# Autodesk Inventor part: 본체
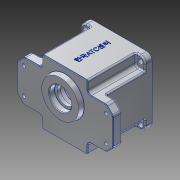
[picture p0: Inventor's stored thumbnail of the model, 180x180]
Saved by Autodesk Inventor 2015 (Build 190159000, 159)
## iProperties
Created: 2016-02
Part Number: 본체
Material: Aluminum 6061
Document SubType Name: Modeling
Designer: Administrator
Density: 2.7 g/cm^3
Appearance: Aluminum - Flat
Mass: 874.124 g
Surface Area: 762.764 cm^2
Volume: 323.75 cm^3
Author: Administrator
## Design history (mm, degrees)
sketch "Sketch1"
  geometry: L1 (-47, -47)-(47, -47); L2 (47, -47)-(47, 47); L3 (47, 47)-(-47, 47); L4 (-47, 47)-(-47, -47); L5 (-47, -47)-(47, 47); L6 (47, -47)-(-47, 47); 1 further point
  constraints: 12 end point, 2 midpoint, 2 parallel, 1 horizontal, 1 perpendicular
  dimensions: "d0" = 94 distance of L3.end L2.end; "d1" = 94 distance of L2.end L1.end
extrude "Extrusion1" new body sketch "Sketch1" distance "d2" = 80; taper "d3" = 0 deg
sketch "Sketch2"
  geometry: L1 (33, -47)-(-33, -47); L2 (-33, -47)-(-33, 47); L3 (-33, 47)-(33, 47); L4 (33, 47)-(33, -47); L5 (33, -47)-(-33, 47); L6 (-33, -47)-(33, 47); L7 (-47, 47)-(47, 47) reference; L8 (47, -30)-(-47, -30); L9 (-47, -30)-(-47, 30); L10 (-47, 30)-(47, 30); L11 (47, 30)-(47, -30); L12 (47, -30)-(-47, 30); L13 (-47, -30)-(47, 30); L14 (47, 47)-(47, -47) reference; L15 (47, -47)-(-47, -47) reference; L16 (-47, -47)-(-47, 47) reference; L17 (-47, 47)-(47, 47) reference; L18 (47, 47)-(47, -47) reference; 1 further point
  constraints: 24 end point, 4 midpoint, 4 parallel, 2 collinear, 2 horizontal, 2 perpendicular
  dimensions: "d4" = 66 distance of L2.end L3.end; "d5" = 60 distance of L8.end L9.end
extrude "Extrusion2" cut sketch "Sketch2" distance "d6" = 70; taper "d7" = 0 deg
sketch "Sketch3"
  geometry: L1 (70, -30)-(-70, -30); L2 (-70, -30)-(-70, 30); L3 (-70, 30)-(70, 30); L4 (70, 30)-(70, -30); L5 (70, -30)-(-70, 30); L6 (-70, -30)-(70, 30); 1 further point
  constraints: 12 end point, 2 midpoint, 2 parallel, 1 horizontal, 1 perpendicular
  dimensions: "d8" = 140 distance of L2.end L3.end; "d9" = 60 distance of L1.end L2.end
extrude "Extrusion3" join sketch "Sketch3" distance "d10" = 13; taper "d11" = 0 deg
fillet "Fillet1" dims "d12" = 8
chamfer "Chamfer1" distance "d13" = 10; stored, may be unused: second distance "d14" = 2, angle "d15" = 45 deg
sketch "Sketch4"
  geometry: C1 r 28 at (0, 11); 1 further point
  constraints: 1 centre point, 1 vertical alignment
  dimensions: "d16" = 56 diameter of C1; "d17" = 11 distance of C1.centre point (0, 0)
extrude "Extrusion4" join sketch "Sketch4" distance "d18" = 7; taper "d19" = -10 deg
sketch "Sketch5"
  geometry: C1 r 43 at (0, 0); 1 further point
  constraints: 1 centre point, 1 coincident
  dimensions: "d20" = 86 diameter of C1
extrude "Extrusion5" cut sketch "Sketch5" distance "d21" = 9; taper "d22" = 0 deg
sketch "Sketch6"
  geometry: C1 r 40 at (0, 0); 1 further point
  constraints: 1 centre point, 1 coincident
  dimensions: "d23" = 80 diameter of C1
extrude "Extrusion6" cut sketch "Sketch6" distance "d24" = 62; taper "d25" = 0 deg
sketch "Sketch7"
  geometry: C1 r 21 at (0, -11); C2 r 15 at (0, 20); 1 further point
  constraints: 2 centre point, 2 vertical alignment
  dimensions: "d26" = 21 radius of C1; "d27" = 15 radius of C2; "d28" = 11 distance of point (0, 0) C1.centre; "d29" = 20 distance of C2.centre point (0, 0)
extrude "Extrusion7" join sketch "Sketch7" distance "d30" = 7; taper "d31" = 0 deg
hole "Hole1" diameter "d34" = 19; stored, may be unused: countersink angle "d38" = 90 deg, drill point angle "d40" = 0 deg; dims "d32" = 10, "d33" = 10, "d35" = 6, "d36" = 22, "d37" = 7, "d39" = 8
sketch "Sketch8"
  geometry: C1 r 17.5 at (0, -11); A1 r 21 centre (0, -11) between (-8.978, 7.984) and (8.978, 7.984) reference; 1 further point
  constraints: 1 centre point, 1 coincident
  dimensions: "d41" = 35 diameter of C1
extrude "Extrusion8" cut sketch "Sketch8" distance "d42" = 10; taper "d43" = 0 deg
hole "Hole2" diameter "d46" = 25; stored, may be unused: countersink angle "d50" = 90 deg, drill point angle "d52" = 0 deg; dims "d44" = 10, "d45" = 10, "d47" = 6, "d48" = 32, "d49" = 8, "d51" = 13
fillet "Fillet2" dims "d53" = 3
sketch "Sketch9"
  geometry: L1 (-35.777, -4)-(-39.799, -4); L2 (-35.777, 4)-(-39.799, 4); L3 (39.799, -4)-(35.777, -4); L4 (39.799, 4)-(35.777, 4); A1 r 36 centre (0, 0) between (36, 0) and (-36, 0); A2 r 40 centre (0, 0) between (-39.799, -4) and (-39.799, 4) reference; A3 r 4 centre (36, 0) between (36, 4) and (36, -4); A4 r 4 centre (-36, 0) between (-36, -4) and (-36, 4); A5 r 40 centre (0, 0) between (39.799, -4) and (39.799, 4); A6 r 40 centre (0, 0) between (-39.799, 4) and (-39.799, -4); 1 further point
  constraints: 18 point on circle, 8 end point, 5 centre point, 4 horizontal, 4 point on line, 4 tangent, 3 coincident, 2 horizontal alignment
  dimensions: "d54" = 36 radius of A1; "d55" = 4 radius of A3; "d56" = 4 radius of A4
extrude "Extrusion9" join sketch "Sketch9" stored distance "d57" = 10; taper "d58" = 0 deg
fillet "Fillet3" dims "d59" = 3.5
sketch "Sketch10"
  geometry: A1 r 4 centre (36, 0) between (35.852, 3.997) and (35.852, -3.997) reference; A2 r 4 centre (-36, 0) between (-35.852, -3.997) and (-35.852, 3.997) reference; 3 further points
  constraints: 2 coincident
hole "Hole3" sketch "Sketch10" at (36, 0), (-36, 0) diameter "d60" = 3.242; stored, may be unused: countersink angle "d64" = 90 deg, drill point angle "d66" = 118 deg; dims "d61" = 7, "d62" = 32, "d63" = 8, "d65" = 9
sketch "Sketch12"
  geometry: 5 further points
  constraints: 2 horizontal alignment, 2 vertical alignment
  dimensions: "d70" = 120 distance of point (60, -19) point (-60, -19); "d71" = 60 horizontal distance of point (0, 0) point (-60, -19); "d72" = 38 distance of point (-60, 19) point (-60, -19); "d73" = 19 vertical distance of point (0, 0) point (-60, -19)
hole "Hole4" sketch "Sketch12" at (60, -19), (60, 19), (-60, -19), (-60, 19) diameter "d74" = 5; stored, may be unused: countersink angle "d78" = 90 deg, drill point angle "d80" = 0 deg; dims "d75" = 6, "d76" = 9, "d77" = 4, "d79" = 13
sketch "Sketch13" dims "d0" = 94, "d1" = 94
  geometry: L1 (0, 0)-(78, 0) reference; 2 further points
  constraints: 1 vertical alignment, 1 other
  dimensions: "d82" = 40 distance from line of L1 point (39, -40)
emboss "Emboss1" sketch "Sketch13" dims "d0" = 94, "d1" = 94, "d83" = 0.5, "d84" = 0
fillet "Fillet4" dims "d85" = 0.3
chamfer "Chamfer2" distance "d86" = 1; stored, may be unused: second distance "d87" = 2, angle "d88" = 45 deg
fillet "Fillet5" dims "d89" = 5
sketch "Sketch14"
  geometry: L1 (-47, -39)-(-47, 39) reference; L2 (-39, 47)-(39, 47) reference; L3 (47, 39)-(47, -39) reference; L4 (39, -47)-(-39, -47) reference; C1 r 3.5 at (-40, 40); C2 r 3.5 at (40, 40); C3 r 3.5 at (40, -40); C4 r 3.5 at (-40, -40); A1 r 8 centre (-39, 39) between (-39, 47) and (-47, 39) reference; A2 r 8 centre (39, 39) between (47, 39) and (39, 47) reference; A3 r 8 centre (39, -39) between (39, -47) and (47, -39) reference; A4 r 8 centre (-39, -39) between (-47, -39) and (-39, -47) reference; A5 r 8 centre (-39, 39) between (-39, 47) and (-47, 39) reference; A6 r 8 centre (39, 39) between (47, 39) and (39, 47) reference; A7 r 8 centre (39, -39) between (39, -47) and (47, -39) reference; 1 further point
  constraints: 4 centre point, 2 horizontal alignment, 2 vertical alignment
  dimensions: "d100" = 7 diameter of C1; "d101" = 7 diameter of C2; "d102" = 7 diameter of C3; "d103" = 7 diameter of C4; "d104" = 80 distance of C2.centre C1.centre; "d105" = 40 horizontal distance of point (0, 0) C2.centre; "d106" = 80 distance of C1.centre C4.centre; "d107" = 40 horizontal distance of point (0, 0) C4.centre
  node "Projected Loop3"
fillet "Fillet6" dims "d96" = 2
sketch "Sketch15"
  geometry: L1 (31, -47)-(-31, -47) reference; L2 (33, -45)-(33, -35) reference; L3 (38, -30)-(57.929, -30) reference; L4 (68.536, -21.464)-(61.464, -28.536) reference; L5 (70, 17.929)-(70, -17.929) reference; L6 (61.464, 28.536)-(68.536, 21.464) reference; L7 (57.929, 30)-(38, 30) reference; L8 (33, 35)-(33, 45) reference; L9 (-31, 47)-(31, 47) reference; L10 (-33, 45)-(-33, 35) reference; L11 (-38, 30)-(-57.929, 30) reference; L12 (-68.536, 21.464)-(-61.464, 28.536) reference; L13 (-70, -17.929)-(-70, 17.929) reference; L14 (-61.464, -28.536)-(-68.536, -21.464) reference; L15 (-57.929, -30)-(-38, -30) reference; L16 (-33, -35)-(-33, -45) reference; L17 (32, 45)-(32, 35); L18 (38, 29)-(57.929, 29); L19 (60.757, 27.828)-(67.828, 20.757); L20 (69, 17.929)-(69, -17.929); L21 (67.828, -20.757)-(60.757, -27.828); L22 (57.929, -29)-(38, -29); L23 (32, -35)-(32, -45); L24 (31, -46)-(-31, -46); L25 (-32, -45)-(-32, -35); L26 (-38, -29)-(-57.929, -29); L27 (-60.757, -27.828)-(-67.828, -20.757); L28 (-69, -17.929)-(-69, 17.929); L29 (-67.828, 20.757)-(-60.757, 27.828); L30 (-57.929, 29)-(-38, 29); L31 (-32, 35)-(-32, 45); L32 (-31, 46)-(31, 46); C1 r 28.252 at (0, 11) reference; C2 r 2.5 at (-60, 19) reference; C3 r 2.5 at (60, 19) reference; C4 r 2.5 at (60, -19) reference; C5 r 2.5 at (-60, -19) reference; A1 r 2 centre (-31, -45) between (-33, -45) and (-31, -47) reference; A2 r 2 centre (31, -45) between (31, -47) and (33, -45) reference; A3 r 5 centre (38, -35) between (38, -30) and (33, -35) reference; A4 r 5 centre (57.929, -25) between (57.929, -30) and (61.464, -28.536) reference; A5 r 5 centre (65, -17.929) between (68.536, -21.464) and (70, -17.929) reference; A6 r 5 centre (65, 17.929) between (70, 17.929) and (68.536, 21.464) reference; A7 r 5 centre (57.929, 25) between (61.464, 28.536) and (57.929, 30) reference; A8 r 5 centre (38, 35) between (33, 35) and (38, 30) reference; A9 r 2 centre (31, 45) between (33, 45) and (31, 47) reference; A10 r 2 centre (-31, 45) between (-31, 47) and (-33, 45) reference; A11 r 5 centre (-38, 35) between (-38, 30) and (-33, 35) reference; A12 r 5 centre (-57.929, 25) between (-57.929, 30) and (-61.464, 28.536) reference; A13 r 5 centre (-65, 17.929) between (-68.536, 21.464) and (-70, 17.929) reference; A14 r 5 centre (-65, -17.929) between (-70, -17.929) and (-68.536, -21.464) reference; A15 r 5 centre (-57.929, -25) between (-61.464, -28.536) and (-57.929, -30) reference; A16 r 5 centre (-38, -35) between (-33, -35) and (-38, -30) reference; A17 r 1 centre (31, 45) between (32, 45) and (31, 46); A18 r 6 centre (38, 35) between (32, 35) and (38, 29); A19 r 4 centre (57.929, 25) between (60.757, 27.828) and (57.929, 29); A20 r 4 centre (65, 17.929) between (69, 17.929) and (67.828, 20.757); A21 r 4 centre (65, -17.929) between (67.828, -20.757) and (69, -17.929); A22 r 4 centre (57.929, -25) between (57.929, -29) and (60.757, -27.828); A23 r 6 centre (38, -35) between (38, -29) and (32, -35); A24 r 1 centre (31, -45) between (31, -46) and (32, -45); A25 r 1 centre (-31, -45) between (-32, -45) and (-31, -46); A26 r 6 centre (-38, -35) between (-32, -35) and (-38, -29); A27 r 4 centre (-57.929, -25) between (-60.757, -27.828) and (-57.929, -29); A28 r 4 centre (-65, -17.929) between (-69, -17.929) and (-67.828, -20.757); A29 r 4 centre (-65, 17.929) between (-67.828, 20.757) and (-69, 17.929); A30 r 4 centre (-57.929, 25) between (-57.929, 29) and (-60.757, 27.828); A31 r 6 centre (-38, 35) between (-38, 29) and (-32, 35); A32 r 1 centre (-31, 45) between (-31, 46) and (-32, 45); 1 further point
  constraints: 32 end point, 32 point on circle, 16 centre point, 31 other
  dimensions: "d97" = 1 distance between parallel lines of L9 L32
extrude "Extrusion12" cut sketch "Sketch15" distance "d98" = 1; taper "d99" = 0 deg
extrude "Extrusion13" cut sketch "Sketch14" stored distance "d108" = 1; taper "d109" = 0 deg
body "Solid1"
node "Projected Loop1"
node "Projected Loop4"
